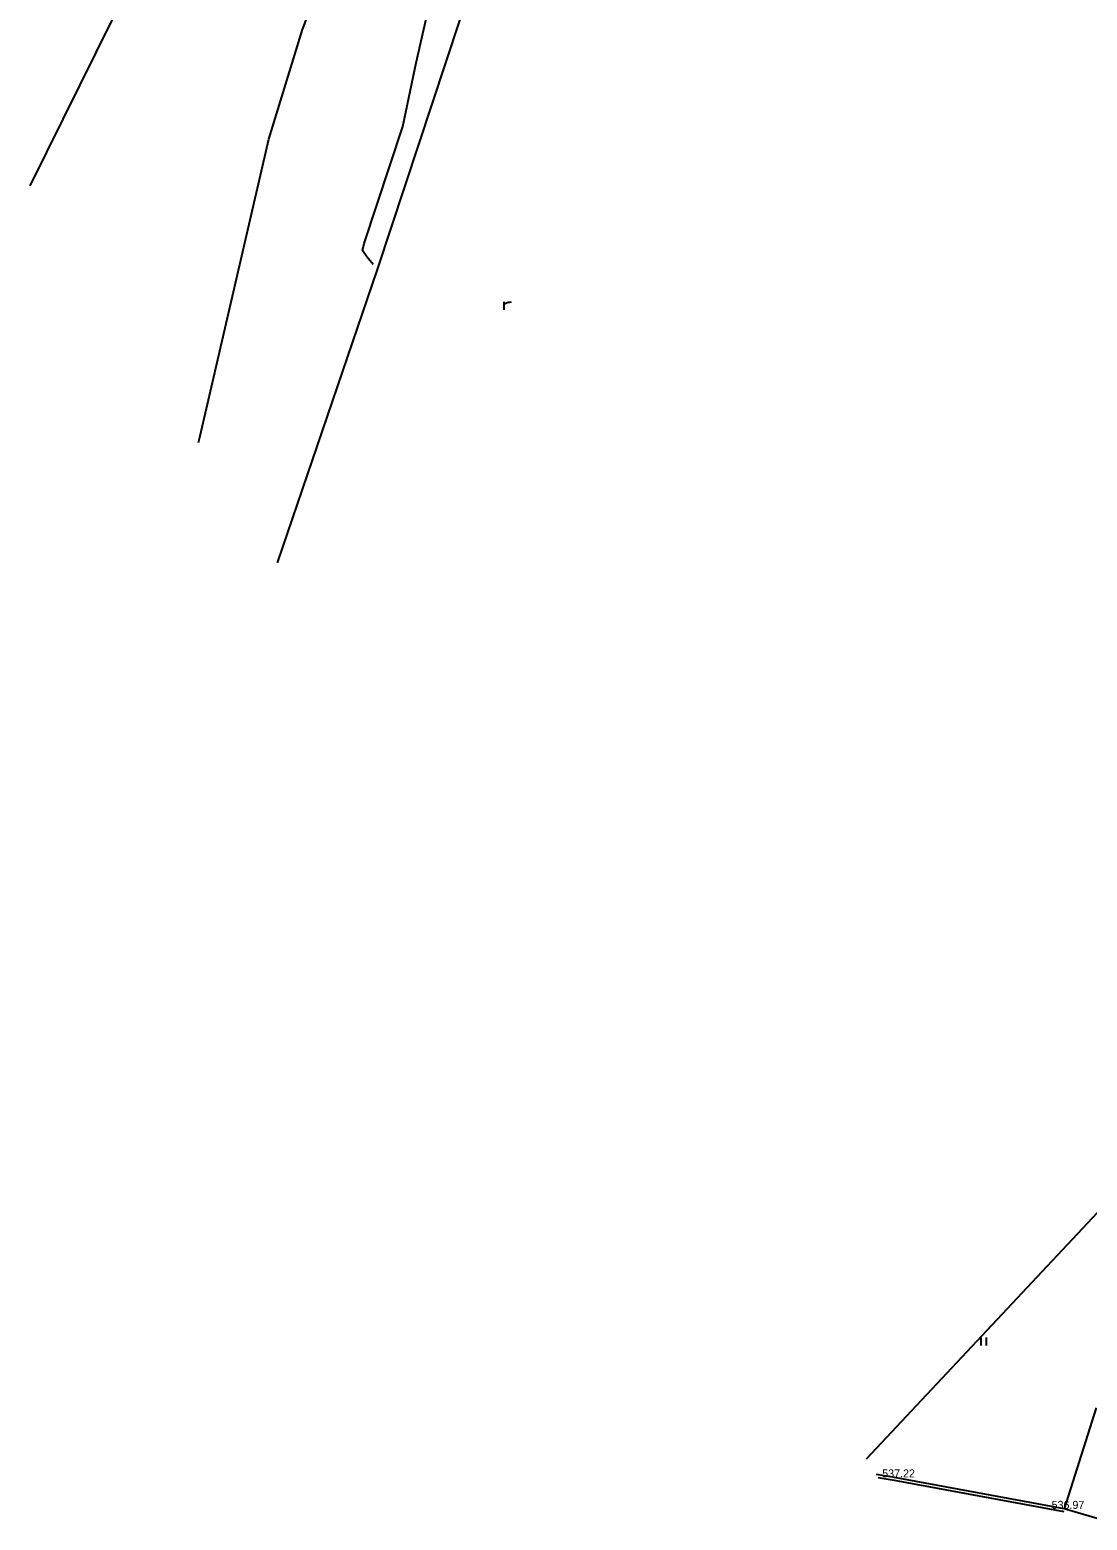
# Model space of a CAD drawing. Extents: x -669393 to -668650, y -1126925 to -1126294.
# Drawn here: x -669346.1 to -669247, y -1126724.9 to -1126585.2 of the extents above; entities that cross this region are included whole.
import ezdxf

# ---------------------------------------------------------------- set-up
doc = ezdxf.new("R2010")
doc.units = 0
for name, color, linetype in [('G_Bod_tecka', 7, 'Continuous'), ('G_Bod_vyska', 7, 'Continuous'), ('G_Cesty_Schody', 7, 'Continuous'), ('G_Ploty', 7, 'Continuous'), ('G_Ploty_vstupy', 7, 'Continuous'), ('G_Z_ELsilove_nadz_kotovane', 7, 'Continuous'), ('G_Z_ELsilove_podz_kotovane', 7, 'Continuous'), ('G_Z_SPOJE_podz_geodeticky', 7, 'Continuous'), ('G_Zelen-okraj', 7, 'Continuous'), ('G_Zelen-Znacky', 7, 'Continuous')]:
    doc.layers.add(name, color=color, linetype=linetype)

msp = doc.modelspace()

# ---------------------------------------------------------------- linework, layer by layer
at = {"layer": 'G_Bod_tecka'}
for p, q in [((-669265.07, -1126720.88), (-669265.07, -1126720.88)), ((-669249.17, -1126723.83), (-669249.17, -1126723.83))]:
    msp.add_line(p, q, dxfattribs=at)
at = {"layer": 'G_Cesty_Schody'}
msp.add_lwpolyline([(-669246.16, -1126714.35), (-669249.17, -1126723.83)], dxfattribs=at)
at = {"layer": 'G_Ploty'}
for p, q in [((-669265.07, -1126720.88), (-669266.8, -1126720.62)), ((-669266.61, -1126720.9), (-669265.11, -1126721.13)), ((-669265.11, -1126721.13), (-669249.22, -1126724.08)), ((-669249.17, -1126723.83), (-669265.07, -1126720.88))]:
    msp.add_line(p, q, dxfattribs=at)
at = {"layer": 'G_Ploty_vstupy'}
msp.add_line((-669245.56, -1126724.89), (-669249.17, -1126723.83), dxfattribs=at)
at = {"layer": 'G_Z_ELsilove_nadz_kotovane'}
for points in [[(-669152.18, -1126545.78), (-669152.06, -1126546.28), (-669174.91, -1126584.26), (-669201.71, -1126629.78), (-669232.87, -1126682), (-669267.74, -1126719.18)], [(-669313.55, -1126607.69), (-669299.41, -1126564.99)], [(-669322.92, -1126635.18), (-669313.55, -1126607.69)]]:
    msp.add_lwpolyline(points, dxfattribs=at)
at = {"layer": 'G_Z_ELsilove_podz_kotovane'}
msp.add_lwpolyline([(-669313.95, -1126607.23), (-669314.54, -1126606.53), (-669314.93, -1126605.92), (-669314.79, -1126605.28), (-669311.16, -1126594.29), (-669309.91, -1126588.33), (-669308.47, -1126581.99), (-669306.88, -1126575.58), (-669305.69, -1126570.29), (-669304.13, -1126566.2), (-669302.69, -1126563.08), (-669302.26, -1126561.71), (-669301.92, -1126559.44), (-669301.88, -1126558.96)], dxfattribs=at)
at = {"layer": 'G_Z_SPOJE_podz_geodeticky'}
msp.add_lwpolyline([(-669330.33, -1126623.91), (-669330.16, -1126623.29), (-669323.72, -1126595.49), (-669320.58, -1126585.22), (-669317.35, -1126576.85), (-669314.18, -1126568.82), (-669310.28, -1126559.22), (-669307, -1126554.89), (-669303.42, -1126553.07), (-669302.68, -1126553.14), (-669300.22, -1126553.06), (-669293.76, -1126552.97)], dxfattribs=at)
at = {"layer": 'G_Zelen-okraj'}
msp.add_lwpolyline([(-669322.5, -1126544.6), (-669324.45, -1126556.05), (-669346.13, -1126599.85)], dxfattribs=at)
at = {"layer": 'G_Zelen-Znacky'}
for p, q in [((-669301.66, -1126611.47), (-669301.66, -1126610.74)), ((-669256.95, -1126708.52), (-669256.95, -1126707.77)), ((-669256.45, -1126708.52), (-669256.45, -1126707.77))]:
    msp.add_line(p, q, dxfattribs=at)
msp.add_lwpolyline([(-669301.66, -1126610.98), (-669301.56, -1126610.88), (-669301.45, -1126610.82), (-669301.3, -1126610.77), (-669301.15, -1126610.75), (-669300.99, -1126610.74)], dxfattribs=at)

# ---------------------------------------------------------------- texts
at = {"layer": 'G_Bod_vyska'}
for s, p in [('537.22', (-669266.23, -1126720.88)), ('536.97', (-669250.35, -1126723.83))]:
    msp.add_text(s, height=0.75, dxfattribs=at).set_placement(p)

doc.saveas('drawing.dxf')
